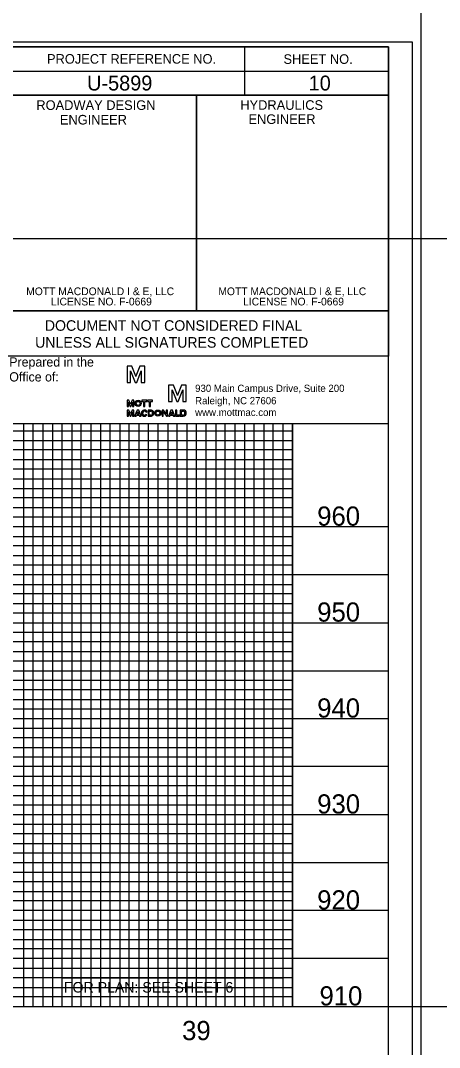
# Model space of a CAD drawing. Extents: x 1967929 to 1975641, y 546296 to 568534.
# Drawn here: x 1971340 to 1971558, y 565788 to 566323 of the extents above; entities that cross this region are included whole.
import ezdxf

# ---------------------------------------------------------------- set-up
doc = ezdxf.new("R2010")
doc.units = 0
for name, color, linetype in [('Exist Vertical Profile Horizontal Axis Label Major', 7, 'Continuous'), ('Exist Vertical Profile Vertical Axis Label', 7, 'Continuous'), ('Old_Level_2', 7, 'Continuous'), ('Old_Level_42', 7, 'Continuous'), ('Old_Level_45', 7, 'Continuous'), ('Prop Grid Mask', 7, 'Continuous'), ('Scratch_Level_1', 7, 'Continuous'), ('Scratch_Level_3', 7, 'Continuous'), ('Sheet Plot Border Inside CELL', 7, 'Continuous'), ('Sheet Plot Border Outside CELL', 7, 'Continuous'), ('Sheet Profile CELL', 7, 'Continuous'), ('Sheet Profile Grid Major CELL', 7, 'Continuous'), ('Sheet Profile Grid Middle CELL', 7, 'Continuous'), ('Sheet Profile Grid Minor CELL', 7, 'Continuous')]:
    doc.layers.add(name, color=color, linetype=linetype)

msp = doc.modelspace()

# ---------------------------------------------------------------- linework, layer by layer
at = {"layer": 'Old_Level_2'}
for p, q in [((1971397.84, 566142.55), (1971395.31, 566142.55)), ((1971395.31, 566142.55), (1971395.31, 566134.05)), ((1971399.89, 566137.3), (1971397.84, 566142.55)), ((1971401.99, 566142.55), (1971399.94, 566137.3)), ((1971404.52, 566142.55), (1971401.99, 566142.55)), ((1971404.52, 566134.05), (1971404.52, 566142.55)), ((1971397.11, 566134.05), (1971397.11, 566140.16)), ((1971397.11, 566140.16), (1971397.13, 566140.16)), ((1971397.13, 566140.16), (1971399.52, 566134.05)), ((1971399.89, 566137.22), (1971399.89, 566137.3)), ((1971399.94, 566137.22), (1971399.89, 566137.22)), ((1971399.94, 566137.3), (1971399.94, 566137.22)), ((1971400.3, 566134.05), (1971402.7, 566140.19)), ((1971402.7, 566140.19), (1971402.72, 566140.19)), ((1971402.72, 566140.19), (1971402.72, 566134.05)), ((1971395.31, 566134.05), (1971397.11, 566134.05)), ((1971399.52, 566134.05), (1971400.3, 566134.05)), ((1971402.72, 566134.05), (1971404.52, 566134.05)), ((1971419.45, 566132.65), (1971416.93, 566132.65)), ((1971416.93, 566132.65), (1971416.93, 566124.15)), ((1971421.5, 566127.4), (1971419.45, 566132.65)), ((1971423.61, 566132.65), (1971421.56, 566127.4)), ((1971426.13, 566132.65), (1971423.61, 566132.65)), ((1971426.13, 566124.15), (1971426.13, 566132.65)), ((1971418.72, 566124.15), (1971418.72, 566130.26)), ((1971418.72, 566130.26), (1971418.75, 566130.26)), ((1971418.75, 566130.26), (1971421.14, 566124.15)), ((1971421.5, 566127.32), (1971421.5, 566127.4)), ((1971421.56, 566127.32), (1971421.5, 566127.32)), ((1971421.56, 566127.4), (1971421.56, 566127.32)), ((1971421.92, 566124.15), (1971424.31, 566130.28)), ((1971424.31, 566130.28), (1971424.34, 566130.28)), ((1971424.34, 566130.28), (1971424.34, 566124.15)), ((1971396.28, 566124.74), (1971395.31, 566124.74)), ((1971395.31, 566124.74), (1971395.31, 566121.5)), ((1971395.31, 566121.5), (1971395.99, 566121.5)), ((1971395.99, 566121.5), (1971395.99, 566123.84)), ((1971395.99, 566123.84), (1971396.02, 566123.84)), ((1971396.02, 566123.84), (1971396.93, 566121.5)), ((1971397.08, 566122.72), (1971396.28, 566124.74)), ((1971396.93, 566121.5), (1971397.24, 566121.5)), ((1971397.89, 566124.74), (1971397.08, 566122.72)), ((1971397.24, 566121.5), (1971398.15, 566123.84)), ((1971398.85, 566124.74), (1971397.89, 566124.74)), ((1971398.15, 566123.84), (1971398.17, 566123.84)), ((1971398.15, 566123.84), (1971398.17, 566123.84)), ((1971398.17, 566123.84), (1971398.17, 566121.5)), ((1971398.17, 566121.5), (1971398.85, 566121.5)), ((1971398.85, 566121.5), (1971398.85, 566124.74)), ((1971408.54, 566124.5), (1971408.56, 566124.5)), ((1971416.93, 566124.15), (1971418.72, 566124.15)), ((1971421.14, 566124.15), (1971421.92, 566124.15)), ((1971424.34, 566124.15), (1971426.13, 566124.15)), ((1971396.28, 566119.7), (1971395.31, 566119.7)), ((1971395.31, 566119.7), (1971395.31, 566116.45)), ((1971395.31, 566116.45), (1971395.99, 566116.45)), ((1971395.99, 566116.45), (1971395.99, 566118.79)), ((1971395.99, 566118.79), (1971396.02, 566118.79)), ((1971396.02, 566118.79), (1971396.93, 566116.45)), ((1971397.08, 566117.67), (1971396.28, 566119.7)), ((1971396.93, 566116.45), (1971397.24, 566116.45)), ((1971397.89, 566119.7), (1971397.08, 566117.67)), ((1971397.24, 566116.45), (1971398.15, 566118.79)), ((1971398.85, 566119.7), (1971397.89, 566119.7)), ((1971398.15, 566118.79), (1971398.17, 566118.79)), ((1971398.17, 566118.79), (1971398.17, 566116.45)), ((1971398.17, 566116.45), (1971398.85, 566116.45)), ((1971398.85, 566116.45), (1971398.85, 566119.7)), ((1971405.67, 566117.12), (1971405.11, 566117.4)), ((1971405.19, 566118.64), (1971405.76, 566118.9)), ((1971407.69, 566119.7), (1971406.2, 566119.7)), ((1971406.2, 566119.7), (1971406.2, 566118.02)), ((1971406.2, 566118.02), (1971406.2, 566116.45)), ((1971406.2, 566116.45), (1971407.69, 566116.45)), ((1971406.88, 566117.08), (1971406.88, 566119.1)), ((1971406.88, 566119.1), (1971407.69, 566119.1)), ((1971407.69, 566117.08), (1971406.88, 566117.08)), ((1971423.02, 566119.7), (1971423.02, 566119.7)), ((1971424.51, 566119.7), (1971423.02, 566119.7)), ((1971423.02, 566119.7), (1971423.02, 566118.02)), ((1971423.02, 566118.02), (1971423.02, 566116.45)), ((1971423.02, 566116.45), (1971424.51, 566116.45)), ((1971423.7, 566117.08), (1971423.7, 566119.1)), ((1971423.7, 566119.1), (1971424.51, 566119.1)), ((1971424.51, 566117.08), (1971423.7, 566117.08)), ((1971424.51, 566119.08), (1971424.51, 566119.08))]:
    msp.add_line(p, q, dxfattribs=at)
for points in [[(1971402.93, 566124.15), (1971403.87, 566124.15), (1971403.87, 566121.5), (1971404.57, 566121.5), (1971404.57, 566124.15), (1971405.5, 566124.15), (1971405.5, 566124.74), (1971402.93, 566124.74), (1971402.93, 566124.15)], [(1971405.92, 566124.15), (1971406.85, 566124.15), (1971406.85, 566121.5), (1971407.56, 566121.5), (1971407.56, 566124.15), (1971408.49, 566124.15), (1971408.49, 566124.74), (1971405.92, 566124.74), (1971405.92, 566124.15)], [(1971399.24, 566116.45), (1971400.02, 566116.45), (1971400.23, 566117), (1971401.63, 566117), (1971401.84, 566116.45), (1971402.59, 566116.45), (1971401.34, 566119.7), (1971400.49, 566119.7), (1971399.24, 566116.45)], [(1971400.41, 566117.6), (1971400.93, 566119), (1971401.45, 566117.6), (1971400.41, 566117.6)], [(1971414.16, 566118.56), (1971414.19, 566118.56), (1971415.75, 566116.45), (1971416.4, 566116.45), (1971416.39, 566119.7), (1971415.72, 566119.7), (1971415.72, 566117.65), (1971414.18, 566119.7), (1971413.51, 566119.7), (1971413.51, 566116.45), (1971414.16, 566116.45), (1971414.16, 566118.56)], [(1971416.81, 566116.45), (1971417.59, 566116.45), (1971417.8, 566117), (1971419.2, 566117), (1971419.41, 566116.45), (1971420.16, 566116.45), (1971418.92, 566119.7), (1971418.06, 566119.7), (1971416.81, 566116.45)], [(1971417.98, 566117.6), (1971418.5, 566119), (1971419.02, 566117.6), (1971417.98, 566117.6)], [(1971422.63, 566116.45), (1971422.63, 566117.03), (1971421.23, 566117.02), (1971421.23, 566119.7), (1971420.55, 566119.7), (1971420.55, 566116.45), (1971422.63, 566116.45)]]:
    msp.add_lwpolyline(points, dxfattribs=at)
msp.add_arc((1971424.51, 566118.08), 1.62, 270, 90, dxfattribs=at)
for centre, major_axis, ratio in [((1971401.06, 566123.12), (0, 1.62), 0.993118), ((1971401.06, 566123.12), (0, 1.06), 0.916103), ((1971411.33, 566118.08), (0, 1.62), 0.993118), ((1971411.33, 566118.08), (0, 1.06), 0.916103)]:
    msp.add_ellipse(centre, major_axis=major_axis, ratio=ratio, dxfattribs=at)
for centre, major_axis, ratio, start_param, end_param in [((1971404.37, 566118.08), (0, 1.62), 0.993118, 5.246647, 10.366427), ((1971404.37, 566118.08), (0, 1.06), 0.916103, 5.276876, 10.296021), ((1971407.69, 566118.08), (0, -1.62), 0.930276, 0, 3.141593), ((1971407.69, 566118.09), (0, -1.01), 0.900832, 0, 3.141593), ((1971424.51, 566118.09), (0, -1.01), 0.900832, 0, 3.141593)]:
    msp.add_ellipse(centre, major_axis=major_axis, ratio=ratio, start_param=start_param, end_param=end_param, dxfattribs=at)
at = {"layer": 'Old_Level_42'}
msp.add_lwpolyline([(1971531.45, 566112.51), (1971331.4, 566112.51), (1971331.4, 566147.81)], dxfattribs=at)
at = {"layer": 'Prop Grid Mask'}
msp.add_lwpolyline([(1971361.53, 565823.9), (1971476.41, 565823.9), (1971476.41, 565813.87), (1971361.53, 565813.87)], close=True, dxfattribs=at)
at = {"layer": 'Scratch_Level_1'}
for p, q in [((1971331.4, 566171.31), (1971531.44, 566171.31)), ((1971531.44, 566171.3), (1971531.44, 566147.8)), ((1971531.44, 566147.81), (1971331.4, 566147.81))]:
    msp.add_line(p, q, dxfattribs=at)
at = {"layer": 'Scratch_Level_3'}
for points in [[(1970081.45, 566308.86), (1970081.45, 565808.86), (1971481.45, 565808.86), (1971481.45, 566112.51), (1971331.4, 566112.51), (1971331.4, 566308.86)], [(1970531.45, 566208.86), (1970531.45, 565808.86), (1971931.45, 565808.86), (1971931.45, 566112.51), (1971781.45, 566112.51), (1971781.45, 566208.86)]]:
    msp.add_lwpolyline(points, close=True, dxfattribs=at)
at = {"layer": 'Sheet Plot Border Inside CELL'}
msp.add_lwpolyline([(1969877.45, 565256.31), (1971543.95, 565256.31), (1971543.95, 566311.41), (1969877.45, 566311.41)], close=True, dxfattribs=at)
at = {"layer": 'Sheet Plot Border Outside CELL'}
msp.add_lwpolyline([(1969864.45, 565233.86), (1971548.45, 565233.86), (1971548.45, 566333.86), (1969864.45, 566333.86)], close=True, dxfattribs=at)
at = {"layer": 'Sheet Profile CELL'}
for p, q in [((1971456.45, 566308.81), (1971456.45, 566283.81)), ((1971331.4, 566296.31), (1971531.45, 566296.31)), ((1971431.45, 566283.81), (1971431.45, 566171.36)), ((1970031.45, 565808.86), (1971531.45, 565808.86))]:
    msp.add_line(p, q, dxfattribs=at)
for points in [[(1971531.45, 566308.86), (1970031.45, 566308.86), (1970031.45, 565258.86), (1971531.45, 565258.86)], [(1971331.4, 566308.86), (1971531.45, 566308.86), (1971531.45, 566283.81), (1971331.4, 566283.81)], [(1971331.4, 566283.81), (1971431.45, 566283.81), (1971431.45, 566171.31), (1971331.4, 566171.31)], [(1971431.45, 566283.81), (1971531.45, 566283.81), (1971531.45, 566171.31), (1971431.45, 566171.31)]]:
    msp.add_lwpolyline(points, close=True, dxfattribs=at)
msp.add_lwpolyline([(1971531.45, 566112.51), (1971331.4, 566112.51), (1971331.4, 566147.81)], dxfattribs=at)
at = {"layer": 'Sheet Profile Grid Major CELL'}
for p, q in [((1970781.45, 566108.86), (1971481.45, 566108.86)), ((1971531.45, 566058.86), (1970781.45, 566058.86)), ((1970781.45, 566008.86), (1971531.45, 566008.86)), ((1971531.45, 565958.86), (1970781.45, 565958.86)), ((1970781.45, 565908.86), (1971531.45, 565908.86)), ((1971531.45, 565858.86), (1970781.45, 565858.86))]:
    msp.add_line(p, q, dxfattribs=at)
for points in [[(1971381.45, 566112.51), (1971381.45, 565808.86), (1971431.45, 565808.86), (1971431.45, 566112.51)], [(1971481.45, 566112.51), (1971481.45, 565808.86), (1971531.45, 565808.86)], [(1971381.45, 566077.21), (1971381.45, 565808.86), (1971431.45, 565808.86), (1971431.45, 566077.21)], [(1971481.45, 566077.21), (1971481.45, 565808.86), (1971531.45, 565808.86)]]:
    msp.add_lwpolyline(points, dxfattribs=at)
at = {"layer": 'Sheet Profile Grid Middle CELL'}
for p, q in [((1970781.45, 566083.86), (1971481.45, 566083.86)), ((1971531.45, 566033.86), (1970781.45, 566033.86)), ((1970781.45, 565983.86), (1971531.45, 565983.86)), ((1971531.45, 565933.86), (1970781.45, 565933.86)), ((1970781.45, 565883.86), (1971531.45, 565883.86))]:
    msp.add_line(p, q, dxfattribs=at)
for points in [[(1971356.45, 566112.51), (1971356.45, 565808.86), (1971406.45, 565808.86), (1971406.45, 566112.51)], [(1971456.45, 566112.51), (1971456.45, 565808.86)], [(1971356.45, 566077.21), (1971356.45, 565808.86), (1971406.45, 565808.86), (1971406.45, 566077.21)], [(1971456.45, 566077.21), (1971456.45, 565808.86)], [(1971531.45, 565833.86), (1970781.45, 565833.86)]]:
    msp.add_lwpolyline(points, dxfattribs=at)
at = {"layer": 'Sheet Profile Grid Minor CELL'}
msp.add_line((1970081.45, 565808.86), (1971481.45, 565808.86), dxfattribs=at)
for points in [[(1971341.45, 566112.51), (1971341.45, 565808.86), (1971346.45, 565808.86), (1971346.45, 566112.51)], [(1971351.45, 566112.51), (1971351.45, 565808.86), (1971361.45, 565808.86), (1971361.45, 566112.51)], [(1971366.45, 566112.51), (1971366.45, 565808.86), (1971371.45, 565808.86), (1971371.45, 566112.51)], [(1971376.45, 566112.51), (1971376.45, 565808.86), (1971386.45, 565808.86), (1971386.45, 566112.51)], [(1971391.45, 566112.51), (1971391.45, 565808.86), (1971396.45, 565808.86), (1971396.45, 566112.51)], [(1971401.45, 566112.51), (1971401.45, 565808.86), (1971411.45, 565808.86), (1971411.45, 566112.51)], [(1971416.45, 566112.51), (1971416.45, 565808.86)], [(1971416.45, 565808.86), (1971421.45, 565808.86), (1971421.45, 566112.51)], [(1971426.45, 566112.51), (1971426.45, 565808.86), (1971436.45, 565808.86), (1971436.45, 566112.51)], [(1971441.45, 566112.51), (1971441.45, 565808.86), (1971446.45, 565808.86), (1971446.45, 566112.51)], [(1971451.45, 566112.51), (1971451.45, 565808.86), (1971461.45, 565808.86), (1971461.45, 566112.51)], [(1971466.45, 566112.51), (1971466.45, 565808.86), (1971471.45, 565808.86), (1971471.45, 566112.51)], [(1971476.45, 566112.51), (1971476.45, 565808.86), (1971486.45, 565808.86)], [(1970781.45, 566103.86), (1971481.45, 566103.86)], [(1971481.45, 566098.86), (1970781.45, 566098.86)], [(1970781.45, 566093.86), (1971481.45, 566093.86)], [(1971481.45, 566088.86), (1970781.45, 566088.86)], [(1970781.45, 566078.86), (1971481.45, 566078.86)], [(1971481.45, 566073.86), (1970781.45, 566073.86)], [(1971341.45, 566077.21), (1971341.45, 565808.86), (1971346.45, 565808.86), (1971346.45, 566077.21)], [(1971351.45, 566077.21), (1971351.45, 565808.86), (1971361.45, 565808.86), (1971361.45, 566077.21)], [(1971366.45, 566077.21), (1971366.45, 565808.86), (1971371.45, 565808.86), (1971371.45, 566077.21)], [(1971376.45, 566077.21), (1971376.45, 565808.86), (1971386.45, 565808.86), (1971386.45, 566077.21)], [(1971391.45, 566077.21), (1971391.45, 565808.86), (1971396.45, 565808.86), (1971396.45, 566077.21)], [(1971401.45, 566077.21), (1971401.45, 565808.86), (1971411.45, 565808.86), (1971411.45, 566077.21)], [(1971416.45, 566077.21), (1971416.45, 565808.86)], [(1971416.45, 565808.86), (1971421.45, 565808.86), (1971421.45, 566077.21)], [(1971426.45, 566077.21), (1971426.45, 565808.86), (1971436.45, 565808.86), (1971436.45, 566077.21)], [(1971441.45, 566077.21), (1971441.45, 565808.86), (1971446.45, 565808.86), (1971446.45, 566077.21)], [(1971451.45, 566077.21), (1971451.45, 565808.86), (1971461.45, 565808.86), (1971461.45, 566077.21)], [(1971466.45, 566077.21), (1971466.45, 565808.86), (1971471.45, 565808.86), (1971471.45, 566077.21)], [(1971476.45, 566077.21), (1971476.45, 565808.86), (1971486.45, 565808.86)], [(1970781.45, 566068.86), (1971481.45, 566068.86)], [(1971481.45, 566063.86), (1970781.45, 566063.86)], [(1970781.45, 566053.86), (1971481.45, 566053.86)], [(1971481.45, 566048.86), (1970781.45, 566048.86)], [(1970781.45, 566043.86), (1971481.45, 566043.86)], [(1971481.45, 566038.86), (1970781.45, 566038.86)], [(1970781.45, 566028.86), (1971481.45, 566028.86)], [(1971481.45, 566023.86), (1970781.45, 566023.86)], [(1970781.45, 566018.86), (1971481.45, 566018.86)], [(1971481.45, 566013.86), (1970781.45, 566013.86)], [(1970781.45, 566003.86), (1971481.45, 566003.86)], [(1971481.45, 565998.86), (1970781.45, 565998.86)], [(1970781.45, 565993.86), (1971481.45, 565993.86)], [(1971481.45, 565988.86), (1970781.45, 565988.86)], [(1970781.45, 565978.86), (1971481.45, 565978.86)], [(1971481.45, 565973.86), (1970781.45, 565973.86)], [(1970781.45, 565968.86), (1971481.45, 565968.86)], [(1971481.45, 565963.86), (1970781.45, 565963.86)], [(1971481.45, 565963.86), (1970881.45, 565963.86)], [(1970781.45, 565953.86), (1971481.45, 565953.86)], [(1971481.45, 565948.86), (1970781.45, 565948.86)], [(1970781.45, 565943.86), (1971481.45, 565943.86)], [(1971481.45, 565938.86), (1970781.45, 565938.86)], [(1970781.45, 565928.86), (1971481.45, 565928.86)], [(1971481.45, 565923.86), (1970781.45, 565923.86)], [(1970781.45, 565918.86), (1971481.45, 565918.86)], [(1971481.45, 565913.86), (1970781.45, 565913.86)], [(1970781.45, 565903.86), (1971481.45, 565903.86)], [(1971481.45, 565898.86), (1970781.45, 565898.86)], [(1970781.45, 565893.86), (1971481.45, 565893.86)], [(1971481.45, 565888.86), (1970781.45, 565888.86)], [(1970781.45, 565878.86), (1971481.45, 565878.86)], [(1971481.45, 565873.86), (1970781.45, 565873.86)], [(1970781.45, 565868.86), (1971481.45, 565868.86)], [(1971481.45, 565863.86), (1970781.45, 565863.86)], [(1970781.45, 565853.86), (1971481.45, 565853.86)], [(1971481.45, 565848.86), (1970781.45, 565848.86)], [(1970781.45, 565843.86), (1971481.45, 565843.86)], [(1971481.45, 565838.86), (1970781.45, 565838.86)], [(1970781.45, 565828.86), (1971481.45, 565828.86)], [(1971481.45, 565823.86), (1970781.45, 565823.86)], [(1970781.45, 565818.86), (1971481.45, 565818.86)], [(1971481.45, 565813.86), (1970781.45, 565813.86)]]:
    msp.add_lwpolyline(points, dxfattribs=at)

# ---------------------------------------------------------------- texts
at = {"layer": 'Exist Vertical Profile Horizontal Axis Label Major'}
msp.add_text('39', height=10, dxfattribs=at).set_placement((1971423.96, 565791.36))
at = {"layer": 'Exist Vertical Profile Vertical Axis Label'}
for s, p in [('960', (1971494.3, 566059.43)), ('950', (1971494.3, 566009.43)), ('940', (1971494.3, 565959.43)), ('930', (1971494.3, 565909.43)), ('920', (1971494.3, 565859.43)), ('910', (1971495.5, 565809.43))]:
    msp.add_text(s, height=10, dxfattribs=at).set_placement(p)
at = {"layer": 'Old_Level_2'}
for s, height, p in [('Prepared in the ', 4.8186, (1971333.95, 566142.31)), ('Office of:', 4.819, (1971333.95, 566134.56))]:
    msp.add_text(s, height=height, dxfattribs=at).set_placement(p)
for s, p in [('930 Main Campus Drive, Suite 200', (1971430.73, 566129.13)), ('Raleigh, NC 27606', (1971430.73, 566122.68)), ('www.mottmac.com', (1971430.73, 566116.59))]:
    msp.add_text(s, height=3.75, rotation=360, dxfattribs=at).set_placement(p)
at = {"layer": 'Old_Level_45'}
for s, p in [('MOTT MACDONALD I & E, LLC', (1971342.76, 566179.54)), ('MOTT MACDONALD I & E, LLC', (1971442.81, 566179.54)), (' LICENSE NO. F-0669', (1971354.15, 566174.19)), (' LICENSE NO. F-0669', (1971454.2, 566174.19))]:
    msp.add_text(s, height=4.0179, dxfattribs=at).set_placement(p)
at = {"layer": 'Prop Grid Mask'}
msp.add_text('FOR PLAN: SEE SHEET 6', height=5.4932, dxfattribs=at).set_placement((1971362.42, 565816.16))
at = {"layer": 'Scratch_Level_1'}
for s, p in [('DOCUMENT NOT CONSIDERED FINAL', (1971352.47, 566160.97)), ('UNLESS ALL SIGNATURES COMPLETED', (1971347.4, 566152.17))]:
    msp.add_text(s, height=5.5, dxfattribs=at).set_placement(p)
at = {"layer": 'Sheet Profile CELL'}
for s, height, p in [('PROJECT REFERENCE NO.', 5.0001, (1971353.6, 566300.16)), ('SHEET NO.', 5, (1971476.75, 566300.06)), ('U-5899', 7.75, (1971374.47, 566286.19)), ('10', 7.75, (1971489.84, 566286.19)), ('ROADWAY DESIGN', 5.0001, (1971348.05, 566276.06)), ('HYDRAULICS', 5, (1971454.25, 566276.11)), ('ENGINEER', 5, (1971360.3, 566268.46)), ('ENGINEER', 5, (1971458.5, 566268.76))]:
    msp.add_text(s, height=height, dxfattribs=at).set_placement(p)

doc.saveas('drawing.dxf')
